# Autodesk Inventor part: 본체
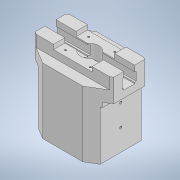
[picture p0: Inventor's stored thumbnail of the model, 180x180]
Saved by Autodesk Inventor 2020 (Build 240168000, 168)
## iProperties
Created: 2023-05
Part Number: 본체
Material: 일반
Document SubType Name: Modeling
Designer: oem
Density: 1 g/cm^3
Appearance: 기본값
Author: oem
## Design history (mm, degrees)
sketch "스케치1"
  geometry: L1 (-40, 0)-(40, 0); L2 (40, 0)-(40, 64); L3 (40, 64)-(42, 64); L4 (42, 64)-(42, 70); L5 (42, 70)-(51, 70); L6 (51, 70)-(51, 100); L7 (51, 100)-(25, 100); L8 (25, 100)-(25, 94); L9 (25, 94)-(-25, 94); L10 (-25, 94)-(-25, 100); L11 (-25, 100)-(-51, 100); L12 (-51, 100)-(-51, 70); L13 (-51, 70)-(-40, 70); L14 (-40, 70)-(-40, 0); 3 further points
  constraints: 28 end point, 12 perpendicular, 2 equal length, 2 midpoint, 1 coincident, 1 horizontal, 1 vertical, 1 vertical alignment
  dimensions: "d0" = 80 distance of L1.start L1.end; "d9" = 64 distance of L1.end L2.end; "d10" = 70 vertical distance of L1.end L5.end; "d11" = 30 distance of L5.end L6.end; "d12" = 70 distance of L13.end L1.start; "d13" = 50 distance between parallel lines of L8 L10; "d14" = 102 distance between parallel lines of L6 L12; "d15" = 6 distance of L7.end L8.end; "d21" = 2 distance of L2.end L3.end
extrude "돌출1" new body sketch "스케치1" distance "d17" = 35; taper "d19" = 0 deg; dims "d18" = 35, "d20" = 0
node "작업 평면1"
sketch "스케치5"
  geometry: L1 (51, -20)-(51, 20); L2 (51, -35)-(51, 35) reference; L3 (-51, -20)-(-51, 20); L4 (-51, -35)-(-51, 35) reference; L5 (26, -35)-(-26, -35); L6 (26, 35)-(-26, 35); L7 (25, -35)-(-25, -35) reference; L8 (-25, 35)-(25, 35) reference; L9 (26, -35)-(51, -20); L10 (51, 20)-(26, 35); L11 (-26, -35)-(-51, -20); L12 (-51, 20)-(-26, 35); L13 (40, -35)-(51, -35) reference; L14 (51, -35)-(51, -20); L15 (51, -35)-(26, -35); L16 (-40, -35)-(40, -35) reference; L17 (-51, -35)-(-42, -35) reference; L18 (-26, -35)-(-51, -35); L19 (-51, -35)-(-51, -20); L20 (-51, 20)-(-51, 35); L21 (-26, 35)-(-51, 35); L22 (40, 35)-(-40, 35) reference; L23 (51, 35)-(40, 35) reference; L24 (51, 20)-(51, 35); L25 (51, 35)-(26, 35); 12 further points
  constraints: 32 end point, 8 midpoint, 4 collinear, 3 vertical, 2 horizontal, 2 perpendicular, 2 point on line
  dimensions: "d23" = 40 distance of L1.start L1.end; "d24" = 40 distance of L3.start L3.end; "d25" = 52 distance of L5.start L5.end; "d26" = 52 distance of L6.start L6.end
extrude "돌출2" cut sketch "스케치5" extent not by distance; stored distance "d27" = 1; taper "d28" = 0 deg
sketch "스케치6"
  geometry: L1 (100, 35)-(85, 35); L2 (85, 35)-(85, 22); L3 (85, 22)-(100, 22); L4 (100, 22)-(100, 35); L5 (100, -22)-(85, -22); L6 (85, -22)-(85, -35); L7 (85, -35)-(100, -35); L8 (100, -35)-(100, -22); 3 further points
  constraints: 16 end point, 4 parallel, 2 coincident, 2 horizontal, 2 perpendicular
  dimensions: "d30" = 13 distance of L3.end L1.start; "d31" = 15 distance of L2.end L3.end; "d32" = 13 distance of L7.end L5.start; "d33" = 15 distance of L6.end L7.end
extrude "돌출3" cut sketch "스케치6" extent not by distance; stored distance "d34" = 36.833; taper "d35" = 0 deg
sketch "스케치7"
  geometry: L1 (100, 7.2)-(100, -7.2); L2 (100, -7.2)-(92.482, -7.2); L3 (92.482, -7.2)-(92, -9); L4 (92, -9)-(81, -9); L5 (81, -9)-(80.518, -7.2); L6 (80.518, -7.2)-(79, -7.2); L7 (79, -7.2)-(79, 7.2); L8 (79, 7.2)-(80.518, 7.2); L9 (80.518, 7.2)-(81, 9); L10 (81, 9)-(92, 9); L11 (92, 9)-(92.482, 7.2); L12 (92.482, 7.2)-(100, 7.2); L13 (100, -22)-(100, 22) reference; 4 further points
  constraints: 24 end point, 6 equal length, 4 midpoint, 3 perpendicular, 2 parallel, 1 collinear, 1 horizontal, 1 vertical, 1 vertical alignment
  dimensions: "d56" = 14.4 distance of L1.start L1.end; "d57" = 18 distance of L3.end L10.end; "d58" = 8 horizontal distance of L3.end L1.end; "d59" = 11 distance of L4.end L3.end; "d61" = 30 deg angle of L5 L3; "d62" = 21 distance of L6.end L1.end; "d63" = 30 deg angle of L9 L11
extrude "돌출4" cut sketch "스케치7" extent not by distance; stored distance "d64" = 51; taper "d65" = 0 deg
sketch "스케치8"
  geometry: L1 (0, 0)-(0, 94); L2 (25, 94)-(-25, 94) reference; L3 (0, 94)-(-12, 94); L4 (-12, 76.03)-(-8, 76.03); L5 (-12, 94)-(-12, 76.03); L6 (-8, 76.03)-(-8, 72.63); L7 (-8, 72.63)-(-10, 72.63); L8 (-10, 72.63)-(-10, 69.43); L9 (-10, 69.43)-(-8, 69.43); L10 (-8, 69.43)-(-8, 66.03); L11 (-8, 66.03)-(-25, 66.03); L12 (-25, 66.03)-(-25, 21.03); L13 (-30, 19.03)-(-30, 13.03); L14 (-30, 13.03)-(-31.5, 13.03); L15 (-31.5, 13.03)-(-31.5, 10.83); L16 (-31.5, 10.83)-(-30, 10.83); L17 (-40, 0)-(-26, 0) reference; L18 (-30, 10.83)-(-30, 0); L19 (-30, 0)-(0, 0); L20 (26, 0)-(-26, 0) reference; L21 (-25, 21.03)-(-25.728, 19.03); L22 (-25.728, 19.03)-(-30, 19.03); 1 further point
  constraints: 38 end point, 10 perpendicular, 5 point on line, 2 collinear, 2 vertical, 1 horizontal, 1 midpoint
  dimensions: "d66" = 24 diameter of L5 L1; "d67" = 20 diameter of L8 L1; "d68" = 16 diameter of L6 L1; "d69" = 50 diameter of L12 L1; "d70" = 60 diameter of L13 L1; "d71" = 63 diameter of L15 L1; "d72" = 17.97002 distance between parallel lines of L4 L3; "d73" = 3.2 distance of L7.end L8.end; "d75" = 45 distance of L11.end L12.end; "d76" = 2 vertical distance of L21.end L12.end; "d77" = 6 distance of L13.start L13.end; "d78" = 2.2 distance of L14.end L15.end; "d79" = 20 deg angle of L21 L12; "d80" = 10 distance of L10.end L4.end
revolve "회전1" sketch "스케치8" stored, may be unused: angle "d81" = 90 deg
sketch "스케치9"
  geometry: 5 further points
  constraints: 2 other
  dimensions: "d82" = 34 distance of point (42.3, -6.841) point (8.3, -6.841); "d83" = 30 distance of point (8.3, -36.841) point (8.3, -6.841)
hole "구멍1" sketch "스케치9" at (8.3, -6.841), (42.3, -6.841), (8.3, -36.841), (43.566, -39.811) diameter "d84" = 2.459; stored, may be unused: countersink angle "d88" = 90 deg, drill point angle "d90" = 118 deg; dims "d85" = 6, "d86" = 4, "d87" = 2, "d89" = 8
sketch "스케치10"
  geometry: L1 (-19.4, 79)-(-33.8, 79) reference; 4 further points
  constraints: 2 vertical alignment, 1 midpoint
  dimensions: "d91" = 28 distance of point (-26.6, 28) point (-26.6, 56); "d92" = 28 distance of point (-26.6, 0) point (-26.6, 28)
hole "구멍2" sketch "스케치10" at (-26.6, 28), (-26.6, 56) diameter "d93" = 3.242; stored, may be unused: countersink angle "d97" = 90 deg, drill point angle "d99" = 118 deg; dims "d94" = 8, "d95" = 4, "d96" = 2, "d98" = 11
sketch "스케치11"
  geometry: L1 (47.667, 100)-(51, 100) reference; L2 (-40, 0)-(-40, 64) reference; 2 further points
  constraints: 1 other
  dimensions: "d100" = 40 distance from line of L1 point (0, 60); "d101" = 40 distance from line of L2 point (0, 60)
feature "엠보싱1" sketch "스케치11" dims "d0" = 80, "d9" = 64, "d10" = 70, "d11" = 30, "d12" = 70, "d13" = 50, "d14" = 102, "d15" = 6, "d21" = 2, "d23" = 40, "d24" = 40, "d25" = 52, "d26" = 52, "d102" = 0.5, "d103" = 0
node "솔리드1"
feature "A9D066F2-1C7D-4E18-AEED-F7BC21143FA4" dims "d84" = 2.459, "d85" = 6, "d86" = 4, "d87" = 2, "d88" = 90 deg, "d89" = 8, "d90" = 118 deg
other parameters: "d22" = 99
